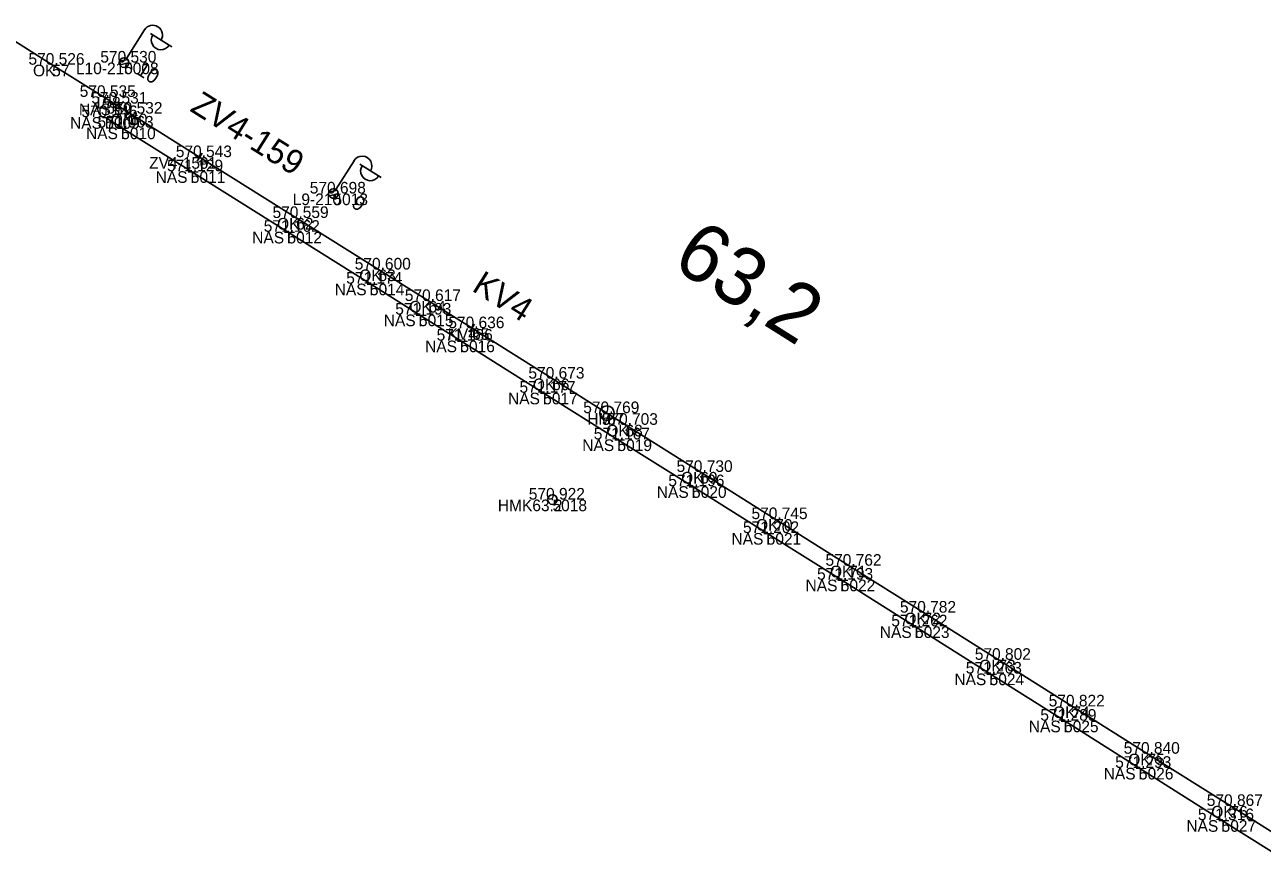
# Model space of a CAD drawing. Extents: x -621782 to -610392, y -1141853 to -1122321.
# Drawn here: x -620519 to -620391, y -1122621.1 to -1122534 of the extents above; entities that cross this region are included whole.
import ezdxf

# ---------------------------------------------------------------- set-up
doc = ezdxf.new("R2010")
doc.units = 0
for name, color, linetype in [('Vrstva 1', 7, 'Continuous'), ('Vrstva 14', 7, 'Continuous'), ('Vrstva 2', 7, 'Continuous'), ('Vrstva 25', 7, 'Continuous'), ('Vrstva 60', 7, 'Continuous'), ('Vrstva 61', 7, 'Continuous'), ('Vrstva 62', 7, 'Continuous'), ('Vrstva 7', 7, 'Continuous')]:
    doc.layers.add(name, color=color, linetype=linetype)

msp = doc.modelspace()

# ---------------------------------------------------------------- linework, layer by layer
at = {"layer": 'Vrstva 1'}
msp.add_lwpolyline([(-620522.74, -1122534), (-620516.18, -1122538.13), (-620510.88, -1122541.46), (-620509.77, -1122542.15), (-620508.12, -1122543.19), (-620500.94, -1122547.69), (-620490.94, -1122553.98), (-620482.44, -1122559.31), (-620477.26, -1122562.56), (-620472.76, -1122565.38), (-620464.48, -1122570.59), (-620458.81, -1122574.16), (-620456.89, -1122575.37), (-620449.16, -1122580.24), (-620441.4, -1122585.12), (-620433.76, -1122589.94), (-620426.06, -1122594.79), (-620418.33, -1122599.67), (-620410.68, -1122604.49), (-620402.92, -1122609.38), (-620394.33, -1122614.78), (-620386.67, -1122619.61)], dxfattribs=at)
at = {"layer": 'Vrstva 14'}
msp.add_lwpolyline([(-620510.69, -1122543.55), (-620509.04, -1122544.63), (-620501.84, -1122549.15), (-620491.85, -1122555.41), (-620483.32, -1122560.77), (-620478.25, -1122563.97), (-620473.97, -1122566.66), (-620465.4, -1122572.05), (-620457.72, -1122576.88), (-620450.01, -1122581.72), (-620442.29, -1122586.56), (-620434.63, -1122591.38), (-620426.95, -1122596.21), (-620419.24, -1122601.09), (-620411.54, -1122605.96), (-620403.8, -1122610.84), (-620395.25, -1122616.25), (-620387.51, -1122621.12)], dxfattribs=at)
at = {"layer": 'Vrstva 2'}
for p, q in [((-620500.67, -1122547.27), (-620501.2, -1122548.12)), ((-620472.49, -1122564.95), (-620473.03, -1122565.8))]:
    msp.add_line(p, q, dxfattribs=at)
at = {"layer": 'Vrstva 25'}
for p, q in [((-620508.48, -1122537.48), (-620506.62, -1122534.52)), ((-620506.02, -1122534.89), (-620503.82, -1122536.27)), ((-620509.23, -1122537.78), (-620508.37, -1122537.58)), ((-620509.18, -1122538.15), (-620508.25, -1122537.94)), ((-620486.83, -1122551.02), (-620484.96, -1122548.06)), ((-620484.37, -1122548.43), (-620482.17, -1122549.81)), ((-620487.57, -1122551.32), (-620486.72, -1122551.12)), ((-620487.53, -1122551.69), (-620486.59, -1122551.48))]:
    msp.add_line(p, q, dxfattribs=at)
for centre in [(-620508.74, -1122537.91), (-620487.09, -1122551.45)]:
    msp.add_circle(centre, 0.5, dxfattribs=at)
for centre, start, end in [((-620505.77, -1122535.05), 327.8645, 147.8645), ((-620504.93, -1122535.59), 147.162, 328.5671), ((-620484.12, -1122548.59), 327.8803, 147.8803), ((-620483.28, -1122549.13), 147.1777, 328.5829)]:
    msp.add_arc(centre, 1, start, end, dxfattribs=at)
at = {"layer": 'Vrstva 60'}
for p, q in [((-620516.18, -1122538.13), (-620516.18, -1122538.13)), ((-620508.74, -1122537.91), (-620508.74, -1122537.91)), ((-620510.88, -1122541.46), (-620510.88, -1122541.46)), ((-620509.77, -1122542.15), (-620509.77, -1122542.15)), ((-620510.69, -1122543.55), (-620510.69, -1122543.55)), ((-620508.12, -1122543.19), (-620508.12, -1122543.19)), ((-620509.04, -1122544.63), (-620509.04, -1122544.63)), ((-620500.94, -1122547.69), (-620500.94, -1122547.69)), ((-620501.84, -1122549.15), (-620501.84, -1122549.15)), ((-620487.09, -1122551.45), (-620487.09, -1122551.45)), ((-620490.94, -1122553.98), (-620490.94, -1122553.98)), ((-620491.85, -1122555.41), (-620491.85, -1122555.41)), ((-620482.44, -1122559.31), (-620482.44, -1122559.31)), ((-620483.32, -1122560.77), (-620483.32, -1122560.77)), ((-620477.26, -1122562.56), (-620477.26, -1122562.56)), ((-620478.25, -1122563.97), (-620478.25, -1122563.97)), ((-620472.76, -1122565.38), (-620472.76, -1122565.38)), ((-620473.97, -1122566.66), (-620473.97, -1122566.66)), ((-620464.48, -1122570.59), (-620464.48, -1122570.59)), ((-620465.4, -1122572.05), (-620465.4, -1122572.05)), ((-620458.81, -1122574.16), (-620458.81, -1122574.16)), ((-620456.89, -1122575.37), (-620456.89, -1122575.37)), ((-620457.72, -1122576.88), (-620457.72, -1122576.88)), ((-620449.16, -1122580.24), (-620449.16, -1122580.24)), ((-620450.01, -1122581.72), (-620450.01, -1122581.72)), ((-620464.44, -1122583.1), (-620464.44, -1122583.1)), ((-620441.4, -1122585.12), (-620441.4, -1122585.12)), ((-620442.29, -1122586.56), (-620442.29, -1122586.56)), ((-620433.76, -1122589.94), (-620433.76, -1122589.94)), ((-620434.63, -1122591.38), (-620434.63, -1122591.38)), ((-620426.06, -1122594.79), (-620426.06, -1122594.79)), ((-620426.95, -1122596.21), (-620426.95, -1122596.21)), ((-620418.33, -1122599.67), (-620418.33, -1122599.67)), ((-620419.24, -1122601.09), (-620419.24, -1122601.09)), ((-620410.68, -1122604.49), (-620410.68, -1122604.49)), ((-620411.54, -1122605.96), (-620411.54, -1122605.96)), ((-620402.92, -1122609.38), (-620402.92, -1122609.38)), ((-620403.8, -1122610.84), (-620403.8, -1122610.84)), ((-620394.33, -1122614.78), (-620394.33, -1122614.78)), ((-620395.25, -1122616.25), (-620395.25, -1122616.25))]:
    msp.add_line(p, q, dxfattribs=at)
at = {"layer": 'Vrstva 7'}
msp.add_line((-620464.48, -1122583.08), (-620464.39, -1122583.13), dxfattribs=at)
for centre, radius in [((-620458.81, -1122574.16), 0.75), ((-620464.44, -1122583.1), 0.5)]:
    msp.add_circle(centre, radius, dxfattribs=at)

# ---------------------------------------------------------------- texts
at = {"layer": 'Vrstva 2'}
for s, rotation, p in [('ZV4-159', 327.8645, (-620502.03, -1122542.86)), ('KV4', 327.8028, (-620472.88, -1122561.45))]:
    msp.add_text(s, height=2.5, rotation=rotation, dxfattribs=at).set_placement(p)
at = {"layer": 'Vrstva 25'}
for s, rotation, p in [('10', 327.8645, (-620507.58, -1122539.02)), ('9', 327.8803, (-620485.33, -1122552.79))]:
    msp.add_text(s, height=1.5, rotation=rotation, dxfattribs=at).set_placement(p)
at = {"layer": 'Vrstva 60'}
for s, p in [('57', (-620516.18, -1122539.33)), ('5008', (-620508.74, -1122539.11)), ('58', (-620510.88, -1122542.66)), ('59', (-620509.77, -1122543.35)), ('5009', (-620510.69, -1122544.75)), ('60', (-620508.12, -1122544.39)), ('5010', (-620509.04, -1122545.83)), ('61', (-620500.94, -1122548.89)), ('5011', (-620501.84, -1122550.35)), ('5013', (-620487.09, -1122552.65)), ('62', (-620490.94, -1122555.18)), ('5012', (-620491.85, -1122556.61)), ('63', (-620482.44, -1122560.51)), ('5014', (-620483.32, -1122561.97)), ('64', (-620477.26, -1122563.76)), ('5015', (-620478.25, -1122565.17)), ('65', (-620472.76, -1122566.58)), ('5016', (-620473.97, -1122567.86)), ('66', (-620464.48, -1122571.79)), ('5017', (-620465.4, -1122573.25)), ('67', (-620458.81, -1122575.36)), ('68', (-620456.89, -1122576.57)), ('5019', (-620457.72, -1122578.08)), ('69', (-620449.16, -1122581.44)), ('5020', (-620450.01, -1122582.92)), ('5018', (-620464.44, -1122584.3)), ('70', (-620441.4, -1122586.32)), ('5021', (-620442.29, -1122587.76)), ('71', (-620433.76, -1122591.14)), ('5022', (-620434.63, -1122592.58)), ('72', (-620426.06, -1122596)), ('5023', (-620426.95, -1122597.41)), ('73', (-620418.33, -1122600.87)), ('5024', (-620419.24, -1122602.29)), ('74', (-620410.68, -1122605.69)), ('5025', (-620411.54, -1122607.16)), ('75', (-620402.92, -1122610.58)), ('5026', (-620403.8, -1122612.04)), ('76', (-620394.33, -1122615.98)), ('5027', (-620395.25, -1122617.45))]:
    msp.add_text(s, height=1.2, dxfattribs=at).set_placement(p)
at = {"layer": 'Vrstva 61'}
for s, p in [('570.526', (-620518.63, -1122538.13)), ('570.530', (-620511.2, -1122537.91)), ('570.535', (-620513.33, -1122541.46)), ('570.531', (-620512.13, -1122542.15)), ('570.546', (-620513.15, -1122543.55)), ('570.532', (-620510.57, -1122543.19)), ('571.063', (-620511.49, -1122544.63)), ('570.543', (-620503.39, -1122547.69)), ('571.129', (-620504.3, -1122549.15)), ('570.698', (-620489.54, -1122551.45)), ('570.559', (-620493.39, -1122553.98)), ('571.162', (-620494.3, -1122555.41)), ('570.600', (-620484.89, -1122559.31)), ('571.174', (-620485.77, -1122560.77)), ('570.617', (-620479.71, -1122562.56)), ('571.193', (-620480.7, -1122563.97)), ('570.636', (-620475.21, -1122565.38)), ('571.186', (-620476.42, -1122566.66)), ('570.673', (-620466.93, -1122570.59)), ('571.177', (-620467.85, -1122572.05)), ('570.769', (-620461.26, -1122574.16)), ('570.703', (-620459.34, -1122575.37)), ('571.167', (-620460.17, -1122576.88)), ('570.730', (-620451.61, -1122580.24)), ('571.196', (-620452.46, -1122581.72)), ('570.922', (-620466.89, -1122583.1)), ('570.745', (-620443.86, -1122585.12)), ('571.202', (-620444.74, -1122586.56)), ('570.762', (-620436.21, -1122589.94)), ('571.193', (-620437.08, -1122591.38)), ('570.782', (-620428.51, -1122594.79)), ('571.262', (-620429.4, -1122596.21)), ('570.802', (-620420.77, -1122599.67)), ('571.263', (-620421.7, -1122601.09)), ('570.822', (-620413.13, -1122604.49)), ('571.289', (-620413.99, -1122605.96)), ('570.840', (-620405.37, -1122609.38)), ('571.293', (-620406.25, -1122610.84)), ('570.867', (-620396.78, -1122614.78)), ('571.316', (-620397.7, -1122616.25))]:
    msp.add_text(s, height=1.2, dxfattribs=at).set_placement(p)
at = {"layer": 'Vrstva 62'}
for s, p in [('OK', (-620518.16, -1122539.33)), ('L10-210', (-620513.72, -1122539.11)), ('NAST', (-620513.41, -1122543.35)), ('L', (-620511.59, -1122542.66)), ('NAST', (-620514.33, -1122544.75)), ('OK', (-620510.11, -1122544.39)), ('NAST', (-620512.68, -1122545.83)), ('ZV4-159', (-620506.15, -1122548.89)), ('NAST', (-620505.48, -1122550.35)), ('L9-210', (-620491.3, -1122552.65)), ('OK', (-620492.92, -1122555.18)), ('NAST', (-620495.49, -1122556.61)), ('OK', (-620484.42, -1122560.51)), ('NAST', (-620486.96, -1122561.97)), ('OK', (-620479.24, -1122563.76)), ('NAST', (-620481.89, -1122565.17)), ('KV4', (-620475.29, -1122566.58)), ('NAST', (-620477.61, -1122567.86)), ('OK', (-620466.47, -1122571.79)), ('NAST', (-620469.04, -1122573.25)), ('HM', (-620460.84, -1122575.36)), ('OK', (-620458.87, -1122576.57)), ('NAST', (-620461.36, -1122578.08)), ('OK', (-620451.14, -1122581.44)), ('NAST', (-620453.65, -1122582.92)), ('HMK63.2', (-620470.09, -1122584.3)), ('OK', (-620443.39, -1122586.32)), ('NAST', (-620445.93, -1122587.76)), ('OK', (-620435.74, -1122591.14)), ('NAST', (-620438.27, -1122592.58)), ('OK', (-620428.04, -1122596)), ('NAST', (-620430.59, -1122597.41)), ('OK', (-620420.31, -1122600.87)), ('NAST', (-620422.88, -1122602.29)), ('OK', (-620412.67, -1122605.69)), ('NAST', (-620415.18, -1122607.16)), ('OK', (-620404.9, -1122610.58)), ('NAST', (-620407.44, -1122612.04)), ('OK', (-620396.32, -1122615.98)), ('NAST', (-620398.89, -1122617.45))]:
    msp.add_text(s, height=1.2, dxfattribs=at).set_placement(p)
at = {"layer": 'Vrstva 7'}
msp.add_text('63,2', height=6, rotation=327.8019, dxfattribs=at).set_placement((-620452.26, -1122558.96))

doc.saveas('drawing.dxf')
